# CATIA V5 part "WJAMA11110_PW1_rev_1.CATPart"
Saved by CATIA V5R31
Part number: WJAMA11110_PW1_rev_1
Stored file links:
  \\solize.local\damia\dept\DDE_Design\10_order\2305701_JAMA_変換検証STEP3_お手本モデル作成\work\02_マツダ_板金\10_CATIA_V5\231211\WJAMA11110_PW1_rev_1.CATPart
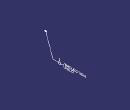
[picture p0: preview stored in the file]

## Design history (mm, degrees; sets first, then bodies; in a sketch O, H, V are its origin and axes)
TTRSSet1
f4a2d38f3ddc11d3a929006094b99c4b_11 "CATTPSSet"
Set1
  Point1: stored without definition
Body1 (main body)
